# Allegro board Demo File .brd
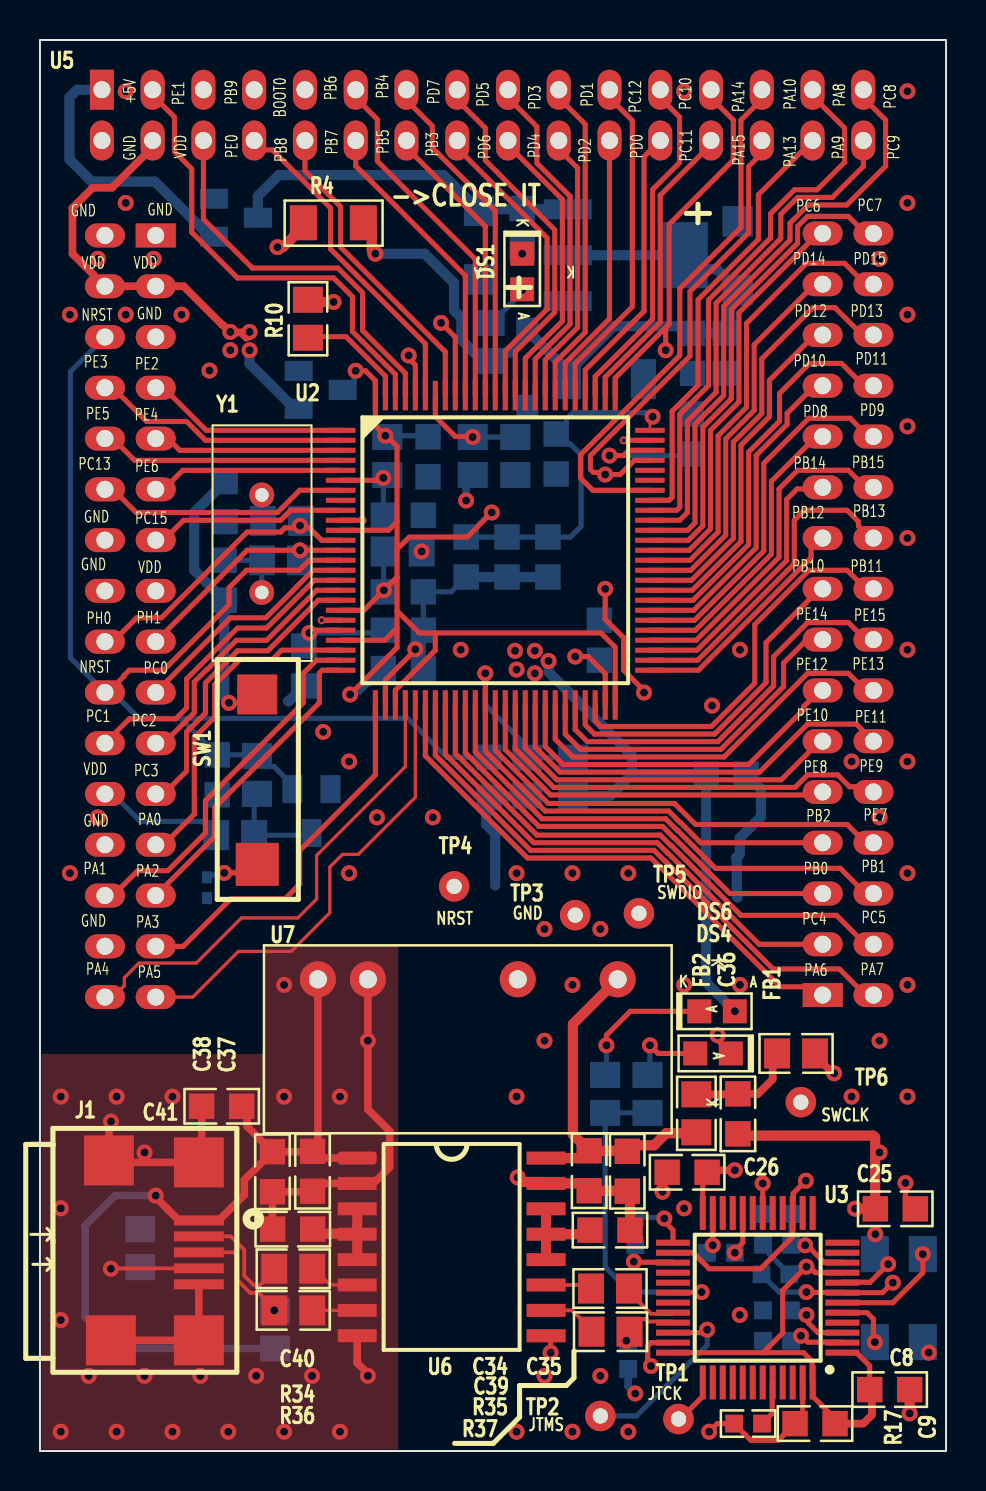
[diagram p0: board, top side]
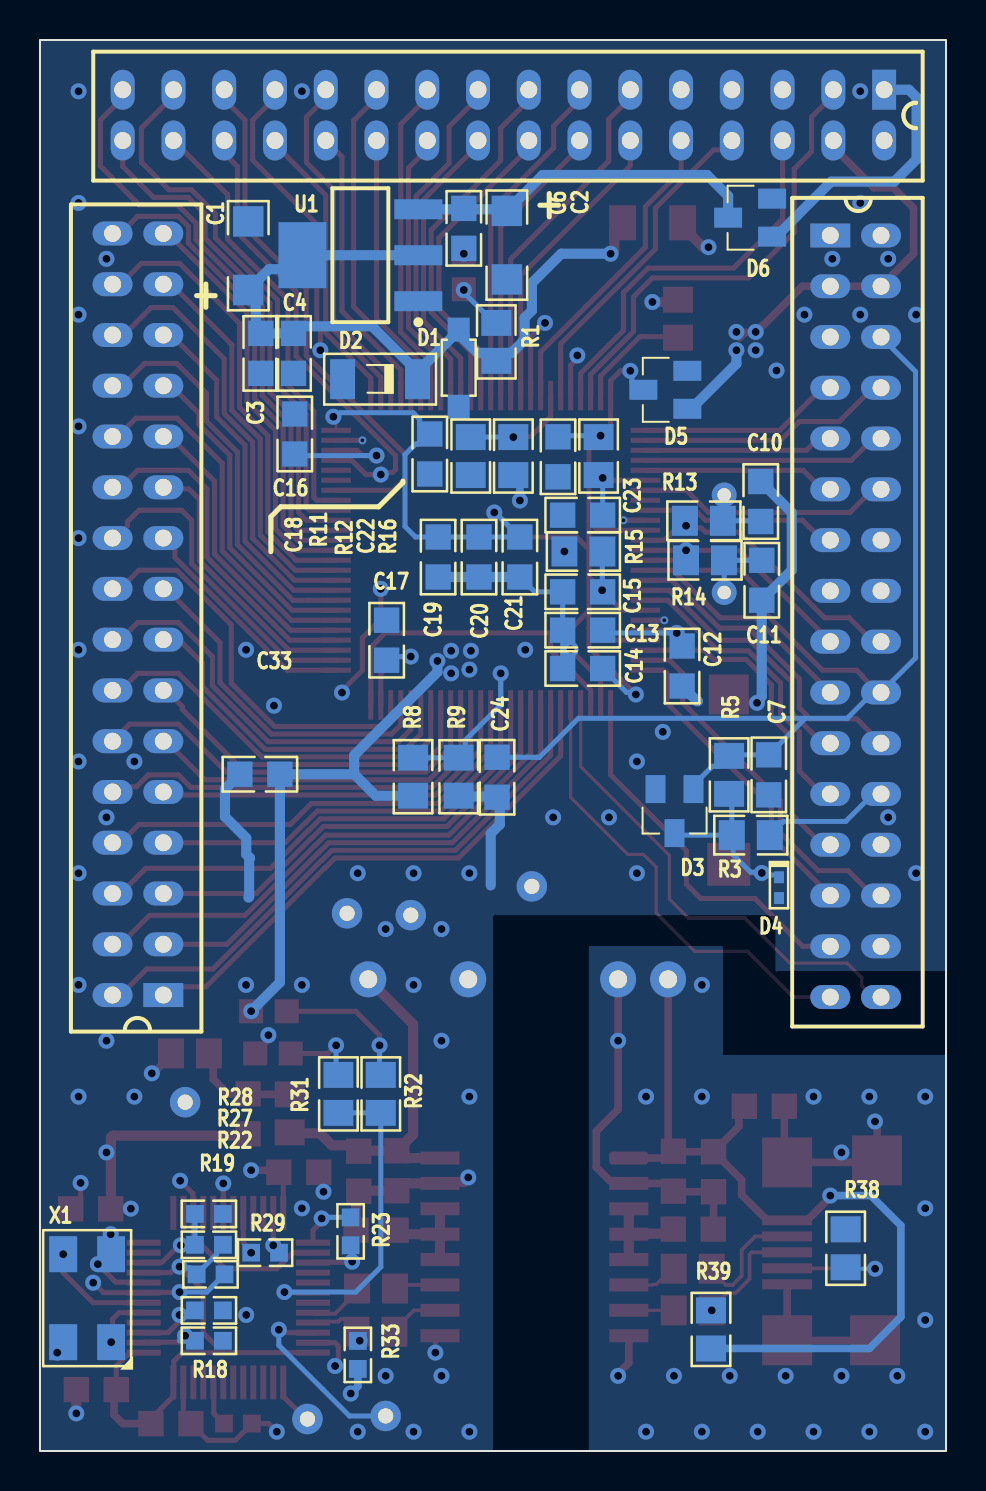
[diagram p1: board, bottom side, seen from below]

Outline 45.34 x 70.59 mm; copper layers: TOP, GND PLANE, L1, BOTTOM. Coordinates in mm from the lower left corner of the outline.
Outline path: rectangle 0,0 45.34,70.59

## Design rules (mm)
constraint set DEFAULT: min track width 0.127

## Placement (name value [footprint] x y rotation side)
C1  -  [CAP-T_1206]  34.92 59.79 90 bottom
C2  -  [CAP-T_1206]  21.97 60.32 270 bottom
C3  -  [CAP_0805]  34.29 54.91 90 bottom
C4  -  [CAP_0805]  32.65 54.91 90 bottom
C6  -  [CAP_0805]  24.13 61.16 90 bottom
C7  -  [CAP_0805]  8.87 33.82 90 bottom
C8  -  [CAP_0805]  42.52 3.07 180 top
C9  -  [CAP_0805]  38.78 1.37 0 top
C10  -  [CAP_0805]  9.27 47.5 90 bottom
C11  -  [CAP_0805]  9.22 43.56 270 bottom
C12  -  [CAP_0805]  13.21 39.27 90 bottom
C13  -  [CAP_0805]  18.18 41.06 180 bottom
C14  -  [CAP_0805]  18.18 39.15 0 bottom
C15  -  [CAP_0805]  18.18 42.98 0 bottom
C16  -  [CAP_0805]  32.59 50.88 270 bottom
C17  -  [CAP_0805]  27.99 40.56 270 bottom
C18  -  [CAP_0805]  25.83 49.88 90 bottom
C19  -  [CAP_0805]  25.42 44.72 90 bottom
C20  -  [CAP_0805]  23.37 44.72 90 bottom
C21  -  [CAP_0805]  21.32 44.72 90 bottom
C22  -  [CAP_0805]  19.42 49.74 90 bottom
C23  -  [CAP_0805]  18.18 46.82 0 bottom
C24  -  [CAP_0805]  22.47 33.71 90 bottom
C25  -  [CAP_0805]  42.8 12.12 0 top
C26  -  [CAP_0805]  32.38 13.94 0 top
C33  -  [CAP_0805]  34.33 33.86 180 bottom
C34  -  [CAP_0805]  27.48 14.02 90 top
C35  -  [CAP_0805]  29.39 14 90 top
C36  -  [CAP_0805]  34.92 16.87 90 top
C37  -  [CAP_0805]  13.64 14 90 top
C38  -  [CAP_0805]  11.63 13.97 90 top
C39  -  [CAP_0805]  28.52 11.05 0 top
C40  -  [CAP_0805]  12.65 11.1 180 top
C41  -  [CAP_0805]  9.09 17.25 180 top
D1  -  [DIO_SOD-123]  24.38 54.17 90 bottom
D2  -  [DIO_SOD80C]  28.32 53.62 0 bottom
D3  -  [SOT_23-3]  13.58 32.01 90 bottom
D4  -  [DIO_0402_SMD]  8.36 28.7 270 bottom
D5  -  [SOT_23-3]  14.05 53.09 180 bottom
D6  -  [SOT_23-3]  9.8 61.7 180 bottom
DS1  -  [LED_0805]  24.13 59 270 top
DS4  -  [LED_0805]  33.68 19.89 180 top
DS6  -  [LED_0805]  33.88 22 0 top
FB1  -  [IND_0805]  37.83 19.89 180 top
FB2  -  [IND_0805]  32.85 16.89 270 top
J1  -  [CON_690-005-299-043]  7.95 13.54 0 top
R1  -  [RES_0805]  22.5 55.48 270 bottom
R3  -  [RES_0805]  9.77 30.81 0 bottom
R4  -  [RES_1206]  14.68 61.44 0 top
R5  -  [RES_0805]  10.86 33.82 270 bottom
R8  -  [RES_0805]  26.67 33.73 90 bottom
R9  -  [RES_0805]  24.38 33.73 270 bottom
R10  -  [RES_0805]  13.41 56.64 270 top
R11  -  [RES_0805]  23.78 49.77 90 bottom
R12  -  [RES_0805]  21.65 49.77 270 bottom
R13  -  [RES_0805]  12.12 46.53 0 bottom
R14  -  [RES_0805]  12.06 44.56 0 bottom
R15  -  [RES_0805]  18.15 45 180 bottom
R16  -  [RES_0805]  17.39 49.77 90 bottom
R17  -  [RES_0603]  35.43 1.37 180 top
R18  -  [RES_0603]  36.88 5.52 180 bottom
R19  -  [RES_0603]  36.88 7.04 180 bottom
R22  -  [RES_0603]  36.8 8.84 0 bottom
R23  -  [RES_0603]  29.79 10.99 270 bottom
R27  -  [RES_0603]  36.88 10.32 0 bottom
R28  -  [RES_0603]  36.88 11.86 0 bottom
R29  -  [RES_0603]  34.07 9.92 0 bottom
R31  -  [RES_0805]  30.4 17.87 270 bottom
R32  -  [RES_0805]  28.28 17.87 270 bottom
R33  -  [RES_0603]  29.43 4.81 90 bottom
R34  -  [RES_0805]  12.67 9.12 180 top
R35  -  [RES_0805]  28.52 8.13 180 top
R36  -  [RES_0805]  12.67 7.04 180 top
R37  -  [RES_0805]  28.55 5.97 180 top
R38  -  [RES_0805]  5.02 10.14 270 bottom
R39  -  [RES_0805]  11.76 6.08 90 bottom
SW1  -  [SW_342_SMD]  10.87 37.85 90 top
TP1  -  [TEST_POINT_30]  31.95 1.6 0 top
TP2  -  [TEST_POINT_30]  28.04 1.75 0 top
TP3  -  [TEST_POINT_30]  26.78 26.81 0 top
TP4  -  [TEST_POINT_30]  20.73 28.24 0 top
TP5  -  [TEST_POINT_30]  29.97 26.9 0 top
TP6  -  [TEST_POINT_30]  38.07 17.45 0 top
U1  -  [SOT223_3]  29.28 59.79 0 bottom
U2  -  [QFN100_19_6_669_58X10_SMD]  22.78 44.93 0 top
U3  -  [LQFP-48_19_6_393_58X11_SMD]  35.92 7.67 180 top
U5  -  [MOD_PRJ-01-07-R070_TH]  5.79 60.81 0 top
U6  -  [SOICW16_50_440_25X76_SMT]  20.6 10.21 0 top
U7  -  [SPU03L-05_100_787_35D70_TH]  28.91 23.6 180 top
X1  -  [ABMM2_94_4_267_71X55_SMD]  42.98 7.65 90 bottom
Y1  -  [XTAL_193_184X455_TH]  11.1 47.83 270 top

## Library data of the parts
C1 C2 = CAP-T_1206
C3 C4 C6-C26 C33-C41 = CAP_0805
D1 = DIO_SOD-123
D2 = DIO_SOD80C
D3 D5 D6 = SOT_23-3
D4 = DIO_0402_SMD
DS1 DS4 DS6 = LED_0805
FB1 FB2 = IND_0805
J1 = CON_690-005-299-043
R1 R3 R5 R8-R16 R31 R32 R34-R39 = RES_0805
R4 = RES_1206
R17-R19 R22 R23 R27-R29 R33 = RES_0603
SW1 = SW_342_SMD
TP1-TP6 = TEST_POINT_30
U1 = SOT223_3
U2 = QFN100_19_6_669_58X10_SMD
U3 = LQFP-48_19_6_393_58X11_SMD
U5 = MOD_PRJ-01-07-R070_TH
U6 = SOICW16_50_440_25X76_SMT
U7 = SPU03L-05_100_787_35D70_TH
X1 = ABMM2_94_4_267_71X55_SMD
Y1 = XTAL_193_184X455_TH

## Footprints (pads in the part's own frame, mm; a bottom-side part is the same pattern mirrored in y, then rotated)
ABMM2_94_4_267_71X55_SMD
  rect 1.8x1.4 smd: 1(-2.2,-1.2) 2(2.2,-1.2) 3(2.2,1.2) 4(-2.2,1.2)
CAP-T_1206
  rect 1.524x1.524 smd: 1(-1.714,-0.005) 2(1.715,-0.005)
CAP_0805
  rect 1.27x1.27 smd: 1(-1,0) 2(1,0)
CON_690-005-299-043
  rect 2.5x0.5 smd: 1(0,-2) 2(0,-2.8) 3(0,-3.6) 4(0,-4.4) 5(0,-5.2)
  rect 2.5x2.5 smd: 6(0,0.9) 6_1(0,-8) 6_2(-4.5,1) 6_3(-4.4,-8)
DIO_0402_SMD
  rect 0.6x0.5 smd: A(1.041,0) K(0,0)
DIO_SOD80C
  rect 1.25x2 smd: A(1.875,0) K(-1.875,0)
DIO_SOD-123
  rect 1.2x1.1 smd: A(-1.938,0.006) K(1.923,0.006)
IND_0805
  rect 1.3x1.5 smd: 1(0.95,0) 2(-0.95,0)
LED_0805
  rect 1.2x1.2 smd: A(0.889,0) K(-0.889,0)
LQFP-48_19_6_393_58X11_SMD
  rect 1.7x0.3 smd: 1(-4.238,2.75) 2(-4.238,2.25) 3(-4.238,1.75) 4(-4.238,1.25) 5(-4.238,0.75) 6(-4.238,0.25) 7(-4.238,-0.25) 8(-4.238,-0.75) 9(-4.238,-1.25) 10(-4.238,-1.75) 11(-4.238,-2.25) 12(-4.238,-2.75) 25(4.238,-2.75) 26(4.238,-2.25) 27(4.238,-1.75) 28(4.238,-1.25) 29(4.238,-0.75) 30(4.238,-0.25) 31(4.238,0.25) 32(4.238,0.75) 33(4.238,1.25) 34(4.238,1.75) 35(4.238,2.25) 36(4.238,2.75)
  rect 0.3x1.7 smd: 13(-2.75,-4.238) 14(-2.25,-4.238) 15(-1.75,-4.238) 16(-1.25,-4.238) 17(-0.75,-4.238) 18(-0.25,-4.238) 19(0.25,-4.238) 20(0.75,-4.238) 21(1.25,-4.238) 22(1.75,-4.238) 23(2.25,-4.238) 24(2.75,-4.238) 37(2.75,4.238) 38(2.25,4.238) 39(1.75,4.238) 40(1.25,4.238) 41(0.75,4.238) 42(0.25,4.238) 43(-0.25,4.238) 44(-0.75,4.238) 45(-1.25,4.238) 46(-1.75,4.238) 47(-2.25,4.238) 48(-2.75,4.238)
MOD_PRJ-01-07-R070_TH
  rect 2x1.2 hole 0.85: 1(0,0) 65(33.376,-37.998)
  oval 2x1.2 hole 0.85: 2(-2.54,0) 3(0,-2.54) 4(-2.54,-2.54) 5(0,-5.08) 6(-2.54,-5.08) 7(0,-7.62) 8(-2.54,-7.62) 9(0,-10.16) 10(-2.54,-10.16) 11(0,-12.7) 12(-2.54,-12.7) 13(0,-15.24) 14(-2.54,-15.24) 15(0,-17.78) 16(-2.54,-17.78) 17(0,-20.32) 18(-2.54,-20.32) 19(0,-22.86) 20(-2.54,-22.86) 21(0,-25.4) 22(-2.54,-25.4) 23(0,-27.94) 24(-2.54,-27.94) 25(0,-30.48) 26(-2.54,-30.48) 27(0,-33.02) 28(-2.54,-33.02) 29(0,-35.56) 30(-2.54,-35.56) 31(0,-38.1) 32(-2.54,-38.1) 66(35.916,-37.998) 67(33.376,-35.458) 68(35.916,-35.458) 69(33.376,-32.918) 70(35.916,-32.918) 71(33.376,-30.378) 72(35.916,-30.378) 73(33.376,-27.838) 74(35.916,-27.838) 75(33.376,-25.298) 76(35.916,-25.298) 77(33.376,-22.758) 78(35.916,-22.758) 79(33.376,-20.218) 80(35.916,-20.218) 81(33.376,-17.678) 82(35.916,-17.678) 83(33.376,-15.138) 84(35.916,-15.138) 85(33.376,-12.598) 86(35.916,-12.598) 87(33.376,-10.058) 88(35.916,-10.058) 89(33.376,-7.518) 90(35.916,-7.518) 91(33.376,-4.978) 92(35.916,-4.978) 93(33.376,-2.438) 94(35.916,-2.438) 95(33.376,0.102) 96(35.916,0.102)
  rect 1.2x2 hole 0.85: 33(-2.692,7.29)
  oval 1.2x2 hole 0.85: 34(-2.692,4.75) 35(-0.152,7.29) 36(-0.152,4.75) 37(2.388,7.29) 38(2.388,4.75) 39(4.928,7.29) 40(4.928,4.75) 41(7.468,7.29) 42(7.468,4.75) 43(10.008,7.29) 44(10.008,4.75) 45(12.548,7.29) 46(12.548,4.75) 47(15.088,7.29) 48(15.088,4.75) 49(17.628,7.29) 50(17.628,4.75) 51(20.168,7.29) 52(20.168,4.75) 53(22.708,7.29) 54(22.708,4.75) 55(25.248,7.29) 56(25.248,4.75) 57(27.788,7.29) 58(27.788,4.75) 59(30.328,7.29) 60(30.328,4.75) 61(32.868,7.29) 62(32.868,4.75) 63(35.408,7.29) 64(35.408,4.75)
QFN100_19_6_669_58X10_SMD
  rect 1.475x0.254 smd: 1(-7.738,6.127) 2(-7.738,5.627) 3(-7.738,5.127) 4(-7.738,4.627) 5(-7.738,4.127) 6(-7.738,3.627) 7(-7.738,3.127) 8(-7.738,2.627) 9(-7.738,2.127) 10(-7.738,1.627) 11(-7.738,1.127) 12(-7.738,0.627) 13(-7.738,0.127) 14(-7.738,-0.373) 15(-7.738,-0.873) 16(-7.738,-1.373) 17(-7.738,-1.873) 18(-7.738,-2.373) 19(-7.738,-2.873) 20(-7.738,-3.373) 21(-7.738,-3.873) 22(-7.738,-4.373) 23(-7.738,-4.873) 24(-7.738,-5.373) 25(-7.738,-5.873) 51(7.738,-5.873) 52(7.738,-5.373) 53(7.738,-4.873) 54(7.738,-4.373) 55(7.738,-3.873) 56(7.738,-3.373) 57(7.738,-2.873) 58(7.738,-2.373) 59(7.738,-1.873) 60(7.738,-1.373) 61(7.738,-0.873) 62(7.738,-0.373) 63(7.738,0.127) 64(7.738,0.627) 65(7.738,1.127) 66(7.738,1.627) 67(7.738,2.127) 68(7.738,2.627) 69(7.738,3.127) 70(7.738,3.627) 71(7.738,4.127) 72(7.738,4.627) 73(7.738,5.127) 74(7.738,5.627) 75(7.738,6.127)
  rect 0.254x1.475 smd: 26(-6,-7.611) 27(-5.5,-7.611) 28(-5,-7.611) 29(-4.5,-7.611) 30(-4,-7.611) 31(-3.5,-7.611) 32(-3,-7.611) 33(-2.5,-7.611) 34(-2,-7.611) 35(-1.5,-7.611) 36(-1,-7.611) 37(-0.5,-7.611) 38(0,-7.611) 39(0.5,-7.611) 40(1,-7.611) 41(1.5,-7.611) 42(2,-7.611) 43(2.5,-7.611) 44(3,-7.611) 45(3.5,-7.611) 46(4,-7.611) 47(4.5,-7.611) 48(5,-7.611) 49(5.5,-7.611) 50(6,-7.611) 76(6,7.865) 77(5.5,7.865) 78(5,7.865) 79(4.5,7.865) 80(4,7.865) 81(3.5,7.865) 82(3,7.865) 83(2.5,7.865) 84(2,7.865) 85(1.5,7.865) 86(1,7.865) 87(0.5,7.865) 88(0,7.865) 89(-0.5,7.865) 90(-1,7.865) 91(-1.5,7.865) 92(-2,7.865) 93(-2.5,7.865) 94(-3,7.865) 95(-3.5,7.865) 96(-4,7.865) 97(-4.5,7.865) 98(-5,7.865) 99(-5.5,7.865) 100(-6,7.865)
RES_0603
  rect 0.889x0.889 smd: 1(-0.699,0) 2(0.699,0)
RES_0805
  rect 1.3x1.5 smd: 1(0.95,0) 2(-0.95,0)
RES_1206
  rect 1.35x1.75 smd: 1(1.5,0) 2(-1.5,0)
SOICW16_50_440_25X76_SMT
  custom 0.163x0.163 smd: 1(-4.725,4.445)
  rect 1.95x0.65 smd: 2(-4.725,3.175) 3(-4.725,1.905) 4(-4.725,0.635) 5(-4.725,-0.635) 6(-4.725,-1.905) 7(-4.725,-3.175) 8(-4.725,-4.445) 9(4.725,-4.445) 10(4.725,-3.175) 11(4.725,-1.905) 12(4.725,-0.635) 13(4.725,0.635) 14(4.725,1.905) 15(4.725,3.175) 16(4.725,4.445)
SOT223_3
  rect 2.4x1 smd: 1(-2.875,2.275) 2(-2.875,-0.025) 3(-2.875,-2.325)
  rect 2.4x3.3 smd: 4(2.925,-0.025)
SOT_23-3
  rect 1.4x1 smd: 1(1.1,-0.95) 2(1.1,0.95) 3(-1.1,0)
SPU03L-05_100_787_35D70_TH
  round 1.8 hole 0.9: 1(15,0) 2(12.5,0) 3(5,0) 4(0,0)
SW_342_SMD
  rect 2x2 smd: 1(0,0)
  rect 2.15x2.15 smd: 2(-8.5,0)
TEST_POINT_30
  round 1.524 hole 0.762: 1(0,0)
XTAL_193_184X455_TH
  round 1.247 hole 0.68: 1(0,0) 2(4.88,0)

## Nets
+3V3: C1.1 C3.2 C4.2 D1.K D2.K R1.1 R4.1 U1.2 U1.4
+5V: C2.1 C6.2 D6.3 U1.3
+5V_P: C34.2 C35.2 FB2.1 U6.16 U7.4
+5V_PBUS: C37.2 C38.2 C41.1 J1.1 R39.2 U6.1 U7.1
GND_IN: C37.1 C38.1 C40.2 C41.2 J1.5 J1.6 J1.6_1 J1.6_2 J1.6_3 R38.2 U6.2 U6.8 U7.2
GND_ISO: C1.2 C2.2 C3.1 C4.1 C6.1 C7.1 C8.1 C9.1 C10.2 C11.2 C12.1 C13.1 C14.2 C15.2 C16.1 C17.1 C18.1 C19.1 C20.1 C21.1 C22.1 C23.2 C24.1 C25.1 C26.1 C33.1 C34.1 C35.1 C36.1 C39.2 D1.A D2.A D4.A DS1.K DS4.K R9.1 R10.2 R11.2 R17.2 R18.2 R19.2 R28.1 R29.1 SW1.1 TP3.1 U1.1 U2.10 U2.20 U2.27 U2.74 U3.8 U3.23 U3.35 U3.47 U5.1 U5.2 U5.5 U5.14 U5.16 U5.26 U5.30 U5.34 U6.9 U6.15 U7.3 X1.2 X1.4
VDD: C8.2 C9.2 C26.2 C33.2 D5.1 DS6.A R3.2 R4.2 R8.2 R12.1 R22.2 R27.1 U3.1 U3.9 U3.24 U3.36 U3.48 U5.3 U5.4 U5.15 U5.24 U5.36
AIN_1: R27.2 R28.2 U3.10
BOOT0: R11.1 R12.2 U2.94 U5.39
D1_N: J1.2 R34.1
D1_P: J1.3 R36.1 R39.1
D3_N: R35.2 U3.32
D3_P: R33.2 R37.2 U3.33
LED_STLINK: R31.1 R32.1 U3.30
NETC10_1: C10.1 R13.2 Y1.1
NETC11_1: C11.1 R14.2 Y1.2
NETC12_2: C12.2 C13.2 R15.2 U2.21
NETC14_1: C14.1 C15.1 C18.2 C19.2 C20.2 C21.2 C22.2 D5.3 R15.1 R16.1 U2.11 U2.19 U2.22 U2.28 U2.50 U2.75 U2.100
NETC16_2: C16.2 U2.73
NETC17_2: C17.2 U2.49
NETC23_1: C23.1 R16.2 U2.6
NETC25_2: C25.2 R22.1 U3.7
NETC36_2: C36.2 FB1.1 FB2.2
NETC39_1: C39.1 U6.12 U6.13 U6.14
NETC40_1: C40.1 U6.3 U6.4 U6.5
NETD3_3: D3.3 D4.K R3.1 R5.1 SW1.2
NETD6_1: D6.1 U5.33
NETDS1_A: DS1.A R1.2
NETDS4_A: DS4.A R31.2
NETDS6_K: DS6.K R32.2
NETFB1_2: FB1.2 R33.1
NETJ1_4: J1.4 R38.1
NETR10_1: R10.1 U2.99
NETR17_1: R17.1 U3.44
NETR18_1: R18.1 U3.2
NETR19_1: R19.1 U3.3
NETR23_1: R23.1 U3.25
NETR29_2: R29.2 U3.20
NETR34_2: R34.2 U6.6
NETR35_1: R35.1 U6.11
NETR36_2: R36.2 U6.7
NETR37_1: R37.1 U6.10
NETU3_5: U3.5 X1.1
NETU3_6: U3.6 X1.3
NRST: C7.2 C24.2 D3.1 R5.2 TP4.1 U2.14 U3.18 U5.6 U5.20
PA0: U2.23 U5.25
PA1: U2.24 U5.28
PA2: U2.25 U5.27
PA3: U2.26 U5.29
PA4: U2.29 U5.32
PA5: U2.30 U5.31
PA6: U2.31 U5.65
PA7: U2.32 U5.66
PA8: U2.67 U5.61
PA9: U2.68 U5.62
PA10: U2.69 U5.59
PA15: U2.77 U5.58
PB0: U2.35 U5.69
PB1: U2.36 U5.70
PB2: R8.1 R9.2 U2.37 U5.71
PB3: U2.89 U5.46
PB4: U2.90 U5.43
PB5: U2.91 U5.44
PB6: U2.92 U5.41
PB7: U2.93 U5.42
PB8: U2.95 U5.40
PB9: U2.96 U5.37
PB10: U2.47 U5.81
PB11: U2.48 U5.82
PB12: U2.51 U5.83
PB13: U2.52 U5.84
PB14: U2.53 U5.85
PB15: U2.54 U5.86
PC0: U2.15 U5.19
PC1: U2.16 U5.22
PC2: U2.17 U5.21
PC3: U2.18 U5.23
PC4: U2.33 U5.67
PC5: U2.34 U5.68
PC6: U2.63 U5.95
PC7: U2.64 U5.96
PC8: U2.65 U5.63
PC9: U2.66 U5.64
PC10: U2.78 U5.55
PC11: U2.79 U5.56
PC12: U2.80 U5.53
PC13: U2.7 U5.12
PC15: U2.9 U5.13
PD0: U2.81 U5.54
PD1: U2.82 U5.51
PD2: U2.83 U5.52
PD3: U2.84 U5.49
PD4: U2.85 U5.50
PD5: U2.86 U5.47
PD6: U2.87 U5.48
PD7: U2.88 U5.45
PD8: U2.55 U5.87
PD9: U2.56 U5.88
PD10: U2.57 U5.89
PD11: U2.58 U5.90
PD12: U2.59 U5.91
PD13: U2.60 U5.92
PD14: U2.61 U5.93
PD15: U2.62 U5.94
PE0: U2.97 U5.38
PE1: U2.98 U5.35
PE2: U2.1 U5.7
PE3: U2.2 U5.8
PE4: U2.3 U5.9
PE5: U2.4 U5.10
PE6: U2.5 U5.11
PE7: U2.38 U5.72
PE8: U2.39 U5.73
PE9: U2.40 U5.74
PE10: U2.41 U5.75
PE11: U2.42 U5.76
PE12: U2.43 U5.77
PE13: U2.44 U5.78
PE14: U2.45 U5.79
PE15: U2.46 U5.80
PH0-OSC_IN: R13.1 U2.12 U5.18
PH1-OSC_OUT: R14.1 U2.13 U5.17
STM_JTCK: TP1.1 U3.37
STM_JTMS: TP2.1 U3.34
SWCLK: TP6.1 U2.76 U3.15 U3.26 U5.57
SWDIO: R23.2 TP5.1 U2.72 U3.27 U5.60

Pads without a net: D3 2; D5 2; D6 2; U2 8 70 71; U3 4 11 12 13 14 16 17 19 21 22 28 29 31 38 39 40 41 42 43 45 46

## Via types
v1: diameter 0.8, hole 0.4, TOP to BOTTOM, 152 vias
v2: diameter 0.4, hole 0.2, TOP to BOTTOM, 3 vias

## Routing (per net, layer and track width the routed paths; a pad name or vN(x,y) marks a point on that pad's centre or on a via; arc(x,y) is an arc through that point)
+3V3: length 37.8
  TOP w0.508: R4.1 16.6,61.02 16.6,60.07 v1(16.78,59.89)
  BOTTOM w0.508: v1(16.78,59.89) 19.25,59.89 20.72,58.42 20.72,57.05 21.09,56.69 21.09,55.58 21.74,54.93 22.11,54.93 R1.1 22.9,54.93 23.44,54.93 24.09,55.58 24.09,55.8 D1.K 24.39,56.05 24.69,55.75 24.69,55.75 26.45,53.99 ; U1.2 U1.4 32.9,59.12 33.87,59.12 C1.1 34.54,57.71 34.54,56.16 C3.2 C4.2 32.3,56.27 28.72,56.27 26.45,53.99 ; 26.45,53.99 D2.K
+5V: length 17.8
  BOTTOM w0.508: U1.3 24.13,62.12 ; 24.13,62.12 C6.2 ; 24.13,62.12 22.06,62.12 C2.1 20.19,63.83 11.95,63.83 10.9,62.78 D6.3
+5V_P: length 18
  TOP w0.508: U6.16 27.12,14.66 C34.2 ; 32.8,15.9 FB2.1 32.8,15.9 ; 32.8,15.9 31.33,15.9 30.73,15.29 29.69,15.29 C35.2 29.36,15.02 C34.2 ; C34.2 26.67,15.84 26.67,21.36 U7.4
+5V_PBUS: length 43.3
  TOP w0.381: U7.1 13.91,15.26 C37.2 ; v1(5.79,12.78) 5.79,12.7 6.95,11.54 J1.1 8.95,11.54 10.23,12.81 10.23,13.56 C38.2 ; C38.2 10.36,16.24 10.36,16.98 C41.1 ; C38.2 13.61,14.97 C37.2 ; U6.1 13.98,14.66 C37.2
  BOTTOM w0.381: R39.2 3.84,5.13 2.26,6.71 2.26,11.28 3.76,12.78 v1(5.79,12.78) 5.89,12.78
GND_IN: length 37.1
  TOP w0.381: 3.66,16.59 v1(3.55,16.48) 3.45,16.38 J1.6_2 3.55,14.44 J1.6 8.09,14.58 C41.2 ; J1.5 J1.6_1 J1.6_3 ; U7.2 v1(16.41,20.52) 16.41,17.09 17.5,16 17.5,14.2 16.82,13.52 16.01,13.52 U6.2 14.03,13.39 13.61,12.97 C38.1 11.63,11.12 C40.2 ; U6.8 15.87,4.41 16.41,3.87 v1(16.41,3.76)
  vias: v1(1.04,17.73) v1(1.04,12.14) v1(1.04,6.55) v1(1.04,0.97) v1(2.44,3.76) v1(3.84,17.73) v1(3.84,0.97) v1(5.23,14.94) v1(5.23,3.76) v1(6.63,17.73) v1(6.63,0.97) v1(8.03,3.76) v1(9.42,0.97) v1(10.82,3.76) v1(12.22,23.32) v1(12.22,17.73) v1(12.22,0.97) v1(13.61,3.76) v1(15.01,17.73) v1(15.01,0.97)
GND_ISO: length 88.6
  TOP w0.254: v1(33.49,0.97) 33.89,1.37 R17.2 35.57,0.53 36.95,0.53 C9.1 38.17,1.75 U3.47 ; v1(9.46,37.43) 10.45,37.43 SW1.1 ; U3.35 30.58,5.42 30.41,5.25 30.41,4.42 v1(30.57,4.26) ; v1(42.44,9.35) 41.54,8.44 40.18,8.44 U3.8 ; v2(14.1,41.56) U2.20 ; v1(33.91,20.8) 33.91,20.55 DS4.K ; v1(31.15,12.97) 31.15,13.71 C26.1 ; v1(25.55,4.92) 25.55,5.57 25.35,5.77 U6.9 ; v1(18.78,40.11) 18.78,40.08 17.28,38.57 U2.27 ; v2(29.2,50.56) U2.74 ; v1(33.67,10.29) U3.23 ; U2.10 v2(16.14,46.56)
  TOP w0.508: C36.1 35.01,15.78 41.69,15.78 41.78,15.69 41.79,15.68 41.79,12.12 ; 41.79,12.12 C25.1 ; 41.79,12.12 v1(40.79,12.12) ; R10.2 13.48,57.66 13.66,57.48 v1(14.69,57.48) ; v1(43.52,1.88) C8.1 ; C39.2 29.52,12.86 C35.1 29.36,13.02 C34.1 27.12,13.39 U6.15 25.25,13.46 24.14,13.46 v1(23.91,13.69)
  BOTTOM w0.254: v1(33.67,10.29) 33.38,10 R29.1 ; 17.2,43 17.2,45 ; C21.1 20.58,42.98 C15.2 C13.1 C14.2
  BOTTOM w0.508: 22.78,28.3 22.78,30.89 22.33,31.34 22.33,32.57 C24.1 22.5,32.74 24.35,32.74 R9.1 ; C21.1 C20.1 C19.1 ; C12.1 12.45,37.51 12.41,37.51 ; C10.2 7.72,46.95 7.72,44.06 C11.2 9.22,37.74 9.46,37.51 v1(9.46,37.43) ; X1.2 41.79,9.86 41.79,10.83 v1(41.8,10.85) ; 34.91,27.69 34.87,27.72 34.87,29.63 34.83,29.67 35.02,29.85 35.02,30.67 36.08,31.73 36.08,33.11 C33.1
  vias: v1(1.5,56.85) v1(1.5,28.91) v1(2.9,59.64) v1(2.9,31.7) v1(4.29,68.02) v1(4.29,62.43) v1(4.29,56.85) v1(5.69,59.64) v1(7.09,56.85) v1(8.48,54.05) v1(15.47,34.49) v1(15.47,28.91) v1(16.87,31.7) v1(19.66,31.7) v1(21.06,40.08) v1(23.85,28.91) v1(23.85,17.73) v1(23.85,0.97) v1(24.13,59.89) v1(25.25,26.11) v1(25.25,20.52) v1(25.25,3.76) v1(26.64,28.91) v1(26.64,23.32) v1(26.64,0.97) v1(28.04,26.11) v1(28.04,3.76) v1(29.44,28.91) v1(29.44,0.97) v1(32.23,68.02) v1(32.23,23.32) v1(32.23,12.14) v1(33.63,37.29) v1(35.03,40.08) v1(35.03,23.32) v1(35.02,6.81) v1(40.61,34.49) v1(40.61,17.73) v1(42.01,59.64) v1(42.01,31.7) v1(42.01,20.52) v1(42.01,14.94) v1(43.41,68.02) v1(43.41,62.43) v1(43.41,56.85) v1(43.41,51.26) v1(43.41,45.67) v1(43.41,40.08) v1(43.41,34.49) v1(43.41,28.91) v1(43.41,23.32) v1(43.41,17.73) v1(44.48,4.92)
VDD: length 162.8
  TOP w0.254: 36.18,4.92 U3.36 ; 36.18,4.92 38.21,4.92 38.64,4.49 38.64,3.46 U3.48 38.67,2.73 39.52,1.88 39.66,1.88 40.17,1.37 C9.2 ; 36.18,4.92 37.17,5.9 37.17,8.03 v1(38.35,9.22) 38.5,9.22 38.8,8.92 U3.9 ; 33.49,14.05 C26.2 33.17,13.73 U3.24 ; U3.1 40.85,4.92 41.52,4.26 C8.2 41.63,2.96
  TOP w0.381: 10.33,55.69 10.07,55.96 9.5,55.96 9.5,55.99 9.16,56.33 9.13,56.33 7.19,58.27 U5.3 U5.4 3.07,58.27 2.69,58.65 2.69,58.82 1.63,59.89 1.63,62.18 2.64,63.2 3.61,63.2 5.64,65.23 U5.36 ; v1(34.77,14.05) 33.49,14.05 ; 40.17,1.37 41.2,1.37 41.63,1.8 41.63,2.96
  TOP w0.508: v1(11.89,60.22) 12.16,60.22 13.18,61.24 R4.2
  L1 w0.381: 34.77,16.15 v1(34.77,22) ; 34.77,16.15 34.85,16.15 37.38,13.62 37.38,9.85 37.93,9.3 38.27,9.3 v1(38.35,9.22) ; 34.77,16.15 v1(34.77,14.05) ; 5.39,43.03 4.04,41.68 2.21,41.68 1.73,41.2 1.73,34.39 2.69,33.42
  L1 w0.508: 20.19,47.55 20.19,44.1 24.77,39.52 v1(25.45,39.52) ; 20.19,47.55 14.68,47.55 10.49,51.74 ; 20.19,47.55 v1(21.32,47.55) ; 10.49,51.74 9.68,50.93 9.68,46.91 6.35,43.58 6.35,43.41 5.97,43.03 U5.15 5.39,43.03 ; 10.49,51.74 v1(10.49,55.07) ; 2.69,33.42 2.69,33.25 3.07,32.87 U5.24 ; v1(10.49,55.98) 10.49,58.83 v1(11.89,60.22)
  BOTTOM w0.254: R3.2 8.82,30.91 8.3,31.43 8.2,31.43 8.13,31.5 5.02,31.5 3.65,32.87 U5.24 ; R27.1 36.5,10 36.5,9.84 R22.2 37.82,9.16 38.29,9.16 v1(38.35,9.22)
  BOTTOM w0.381: v1(21.32,47.55) 21.32,48.5 21.65,48.82 R12.1
  BOTTOM w0.508: 29.62,33.86 28.54,32.78 R8.2 ; 29.62,33.86 29.62,34.8 25.45,38.97 v1(25.45,39.52) ; 29.62,33.86 C33.2 33.33,23.44 v1(34.77,22) ; 12.99,52.09 D5.1 12.75,52.14 10.49,54.39 v1(10.49,55.07)
  vias: v1(9.52,55.98) v1(9.52,55.07) v1(23.77,40.03) v1(23.85,39.09) v1(24.77,40.03) v1(24.77,38.9)
AIN_1: length 4.5
  TOP w0.254: v1(38.29,10.29) 38.38,10.29 39.23,9.44 40.13,9.44 U3.10
  BOTTOM w0.254: R28.2 R27.2 38.27,10.32 v1(38.29,10.29)
BOOT0: length 27.9
  TOP w0.254: U2.94 19.78,51.75 20.78,50.75 21.62,50.75 v1(21.65,50.72)
  L1 w0.254: v1(21.65,50.72) 20.78,50.72 19.76,51.74 19.76,55.35 12.04,63.07 12.04,66.38 10.72,67.7 U5.39
  BOTTOM w0.254: R11.1 v1(21.65,50.72)
D1_N: length 5.9
  TOP w0.19: R34.1 11.72,9.02 11.01,8.31 10.68,8.31 10.23,8.76 10.23,10.06 9.54,10.74 J1.2
D1_P: length 5.8
  TOP w0.19: J1.3 9.72,9.94 9.83,9.83 9.83,8.6 10.52,7.91 10.97,7.91 10.97,7.89 11.72,7.14 v1(11.72,7.04)
D3_N: length 2.8
  TOP w0.19: R35.2 30.03,7.57 30.03,7.41 30.57,6.87 31.62,6.87 U3.32
D3_P: length 3
  TOP w0.19: v1(29.34,5.52) R37.2 29.5,6.04 30.05,6.6 30.29,6.6 30.41,6.47 31.62,6.47 U3.33
LED_STLINK: length 16.6
  TOP w0.254: U3.30 33.08,7.92 v1(33.11,7.95)
  BOTTOM w0.254: R31.1 30.4,16.92 R32.1 28.28,9.21 29.54,7.95 v1(33.11,7.95)
NETC10_1: length 3.7
  TOP w0.254: 11.1,47.33 Y1.1
  BOTTOM w0.254: C10.1 9.31,46.53 R13.2 11.1,46.6 Y1.1
NETC11_1: length 3.5
  BOTTOM w0.254: Y1.2 11.1,44.41 R14.2 C11.1
NETC12_2: length 14.5
  TOP w0.254: U2.21 13.61,41.06 v1(13.48,40.92)
  L1 w0.254: v1(13.48,40.92) 16.46,40.92 19.1,43.56 v1(19.1,45)
  BOTTOM w0.254: 17.04,40.92 v1(13.48,40.92) 13.21,40.66 C12.2 ; 17.04,40.92 C13.2 17.04,40.92
NETC14_1: length 77.4
  TOP w0.127: U2.75 30.52,51.6 v1(30.66,51.74)
  TOP w0.254: U2.50 28.78,40.21 28.07,40.92 19.78,40.92 ; 17.87,46.49 17.87,50.26 17.34,50.79 v1(17.28,50.79) 16.78,51.29 U2.100 16.78,53.54 16.29,54.04 v1(15.8,54.04) ; 17.87,46.49 17.44,46.06 U2.11 ; 17.87,46.49 17.87,45.1 ; 17.87,43.72 17.87,45.1 ; 17.87,43.72 v1(17.21,43.06) 16.21,42.06 U2.19 ; 17.87,43.72 17.87,42.03 ; 17.87,45.1 18.48,45.72 21.38,45.72 v1(22.61,46.95) ; 17.87,41.17 17.87,40.19 v1(15.52,37.85) ; 17.87,41.17 17.26,40.56 U2.22 ; 17.87,41.17 17.87,42.03 ; 19.78,40.92 18.97,40.92 17.87,42.03 ; 19.78,40.92 19.78,40.06 17.78,38.06 U2.28 ; v1(30.66,51.74) 30.66,51.75
  BOTTOM w0.254: v1(17.21,43.06) 17.2,43.06 ; v1(15.52,37.85) 15.62,37.95 15.99,37.95 C14.1 ; C22.2 19.36,50.79 v1(17.28,50.79) ; v1(22.61,46.95) 22.55,46.95 C21.2 C20.2 C19.2 26.54,45.72 27.08,46.25 27.08,49.84 26.8,50.12 26.55,50.37 26.47,50.37 26.29,50.55 26.29,50.63 C18.2 26.34,51.38 26.34,51.61 26.67,51.94 30.31,51.94 30.51,51.74 v1(30.66,51.74) ; C15.1 17.2,43 ; D5.3 15.35,53.09 15.72,53.46 15.72,53.96 v1(15.8,54.04)
NETC16_2: length 6.3
  TOP w0.254: v1(28.5,49.8) 29.2,49.8 29.47,50.06 U2.73
  BOTTOM w0.254: C16.2 32.51,49.8 v1(28.5,49.8)
NETC17_2: length 4.7
  TOP w0.254: v1(26.78,39.74) 27.44,39.74 28.28,38.89 U2.49
  BOTTOM w0.254: v1(26.78,39.74) 27.81,39.74 C17.2
NETC23_1: length 7
  TOP w0.254: v1(17.18,48.68) 17.06,48.56 U2.6
  BOTTOM w0.127: R16.2 17.18,48.62 C23.1
  BOTTOM w0.254: 17.39,48.68 v1(17.18,48.68) 17.32,48.82 R16.2 ; 17.39,48.68 R16.2 ; 17.39,48.68 17.18,48.48 C23.1 ; 17.39,48.68 R16.2
NETC25_2: length 14
  TOP w0.254: v1(42.68,8.42) 42.66,8.42 42.16,7.92 U3.7 40.14,7.94 38.37,7.94 v1(38.35,7.95) ; C25.2 43.31,12.61 v1(43.31,13.41)
  L1 w0.254: v1(43.31,13.41) 43.31,9.05 v1(42.68,8.42)
  BOTTOM w0.254: 38.41,7.95 v1(38.35,7.95) 37,7.95 R22.1
NETC36_2: length 5.5
  TOP w0.381: FB1.1 36.67,19.67 36.67,18.6 35.93,17.87 C36.2 34.9,17.84 FB2.2
NETC39_1: length 4.8
  TOP w0.508: C39.1 27.32,10.85 U6.13 ; U6.13 U6.14 ; U6.13 U6.12
NETC40_1: length 4.9
  TOP w0.508: U6.4 U6.3 ; U6.4 15.85,10.87 13.88,10.87 C40.1 ; U6.4 U6.5
NETD3_3: length 10.7
  TOP w0.254: SW1.2 10.44,28.92 v1(9.22,28.92)
  BOTTOM w0.254: R5.1 10.72,32.74 R3.1 ; 9.26,28.96 9.12,28.81 8.47,28.81 D4.K ; 9.26,28.96 9.78,28.96 10.65,29.83 10.65,30.74 R3.1 ; 9.26,28.96 v1(9.22,28.92) ; R3.1 13.48,30.81 D3.3
NETD6_1: length 13.7
  BOTTOM w0.508: U5.33 1.85,68.1 1.47,67.72 1.47,64.62 2.59,63.5 5.75,63.5 8.5,60.75 D6.1
NETDS1_A: length 2.4
  BOTTOM w0.254: v1(24.13,58.08) 24.13,57.96 22.6,56.43 R1.2
NETDS4_A: length 4
  TOP w0.254: v1(30.52,20.29) 30.93,19.89 DS4.A
  BOTTOM w0.254: R31.2 30.4,18.82 30.52,18.93 v1(30.52,20.29)
NETDS6_K: length 7.2
  TOP w0.254: v1(28.35,20.29) 28.35,20.8 29.54,22 DS6.K
  BOTTOM w0.254: v1(28.35,20.29) 28.35,18.88 R32.2
NETFB1_2: length 28.4
  TOP w0.381: 38.32,20.35 FB1.2 38.78,19.79 39.68,18.89 v1(39.74,18.89)
  L1 w0.381: v1(29.79,2.88) 37.98,2.88 39.75,4.65 39.75,18.75 v1(39.74,18.89)
  BOTTOM w0.381: R33.1 29.43,3.23 v1(29.79,2.88)
NETJ1_4: length 5.9
  TOP w0.19: J1.4 3.57,9.14 v1(3.55,9.12)
  BOTTOM w0.19: R38.1 4.95,9.12 v1(3.55,9.12)
NETR10_1: length 5.8
  TOP w0.254: U2.99 17.28,53.78 15.31,55.74 13.41,55.74 ; 13.41,55.74 13.38,55.74 ; 13.41,55.74 R10.1
NETR17_1: length 2.3
  TOP w0.254: U3.44 36.64,3.41 36.64,1.88 R17.1
NETR18_1: length 3.2
  TOP w0.254: U3.2 40.13,5.44 38.42,5.44 38.1,5.77 v1(38.08,5.77)
  BOTTOM w0.254: R18.1 37.83,5.77 v1(38.08,5.77) 38.1,5.77 38.35,5.51
NETR19_1: length 3.2
  TOP w0.254: U3.3 38.93,5.92 38.46,6.39 38.46,6.7 v1(38.35,6.81)
  BOTTOM w0.254: v1(38.35,6.81) 37.81,6.81 R19.1
NETR23_1: length 2.9
  TOP w0.254: v1(31.24,11.63) 31.24,11.49 31.68,11.05 U3.25
  BOTTOM w0.254: v1(31.24,11.63) 31.19,11.69 R23.1
NETR29_2: length 2.2
  TOP w0.254: v1(34.77,9.92) 34.77,10.03 35.17,10.42 U3.20
NETR34_2: length 2.6
  TOP w0.162: R34.2 13.72,9.12 14.5,8.33 14.67,8.33 14.69,8.31 U6.6
NETR35_1: length 2.3
  TOP w0.19: R35.1 27.4,8.31 U6.11
NETR36_2: length 2.3
  TOP w0.162: R36.2 U6.7
NETR37_1: length 2.8
  TOP w0.19: U6.10 26.63,7.04 27.6,6.07 27.6,5.97 R37.1
NETU3_5: length 2.9
  TOP w0.254: v1(41.78,5.45) 41.71,5.52 41.71,6.6 41.38,6.92 U3.5
NETU3_6: length 5.6
  TOP w0.254: U3.6 42.68,7.42 44.18,8.92 v1(44.18,9.85)
NRST: length 121.8
  TOP w0.254: U3.18 v1(36.17,13.39) ; U5.20 3.4,37.95 4.19,38.74 4.19,38.78 4.47,39.06 6.18,39.06 9.46,42.33 9.46,43.18 10.33,44.06 12.98,44.06 13.48,44.56 U2.14
  L1 w0.254: TP4.1 20.73,25.84 ; 20.73,25.84 9.92,36.65 4.95,36.65 3.65,37.95 U5.20 ; 20.73,25.84 21.32,25.25 21.32,22.88 25.55,18.65 25.55,10.85 28.4,8 31.97,8 32.86,8.89 35.48,8.89 36.17,9.57 v1(36.17,13.39)
  BOTTOM w0.254: C24.2 20.48,34.71 20.46,34.69 20.36,34.69 18.4,36.65 7.04,36.65 ; 7.04,36.65 C7.2 10.8,34.82 R5.2 11.38,34.25 11.7,34.25 12.63,33.31 D3.1 ; 7.04,36.65 4.95,36.65 3.65,37.95 U5.20 3.11,37.95 2.67,38.38 2.67,38.53 1.52,39.67 1.52,54 2.67,55.15 2.67,55.29 3.11,55.73 U5.6
PA0: length 16.5
  TOP w0.254: U5.25 6.19,30.33 7.72,31.86 7.72,35.69 8.74,36.71 8.74,38.33 10.01,39.6 11.63,39.6 12.09,40.06 U2.23
PA1: length 18.5
  TOP w0.254: U5.28 3.65,27.79 4.9,29.03 6.4,29.03 8.28,30.92 8.28,32.53 13.18,37.43 13.18,38.9 13.83,39.56 U2.24
PA2: length 15.7
  TOP w0.254: U2.25 14.13,39.06 13.98,38.91 13.98,37.43 8.74,32.19 8.74,30.74 6.37,28.37 6.37,28.22 5.94,27.79 U5.27
PA3: length 19
  TOP w0.254: U5.29 7.17,25.25 9.56,27.64 12.28,27.64 13,28.35 13,30.04 16.78,33.82 U2.26
PA4: length 24.4
  TOP w0.162: U2.29 18.28,34.23 13.84,29.79 13.84,27.61 12.9,26.67 10.08,26.67 7.82,24.41 4.95,24.41 4.22,23.68 4.22,23.28 3.65,22.71 U5.32
PA5: length 23.1
  TOP w0.162: U5.31 7.65,22.71 9.93,24.99 12.57,24.99 14.5,26.92 14.5,29.21 15.14,29.84 15.93,29.84 18.78,32.7 U2.30
PA6: length 27.4
  TOP w0.254: U2.31 19.28,34.78 24.39,29.67 30.57,29.67 31.09,29.15 31.11,29.15 37.04,23.22 38.75,23.22 U5.65
PA7: length 29.4
  TOP w0.254: U2.32 19.78,34.82 24.55,30.05 30.73,30.05 31.25,29.53 31.27,29.53 36.68,24.11 40,24.11 41.31,22.81 U5.66
PA8: length 27.2
  TOP w0.254: U2.67 31.87,47.06 32.02,47.21 32.02,51.86 33.45,53.3 33.45,57.58 36.56,60.69 36.56,61.9 37.76,63.09 38.89,63.09 40.27,64.47 40.27,66.18 39.4,67.05 38.66,67.79 U5.61
PA9: length 22
  TOP w0.254: U2.68 31.49,47.56 31.63,47.71 31.63,52.02 32.93,53.32 32.93,57.6 35.95,60.61 35.95,62.85 38.08,64.98 38.22,64.98 38.66,65.41 U5.62
PA10: length 26.9
  TOP w0.254: U2.69 27.67,48.06 27.05,48.68 27.05,49.84 32.02,54.81 32.02,58.15 35.08,61.21 35.08,66.58 36.12,67.62 U5.59
PA15: length 15
  TOP w0.254: U2.77 28.28,53.72 31.04,56.47 31.04,62.82 33.58,65.36 U5.58
PB0: length 23.2
  TOP w0.254: U2.35 21.28,34.93 24.97,31.25 31.15,31.25 31.72,30.67 31.74,30.67 34.52,27.89 U5.69
PB1: length 25.2
  TOP w0.254: U2.36 21.78,34.97 25.13,31.63 31.31,31.63 31.88,31.05 31.9,31.05 33.8,29.15 40.05,29.15 41.31,27.89 U5.70
PB2: length 30.1
  TOP w0.254: v1(22.28,38.9) U2.37 22.28,35.01 25.28,32.01 31.46,32.01 32.04,31.44 32.06,31.44 33.06,30.43 U5.71
  BOTTOM w0.254: R8.1 R9.2 24.05,35.01 24.05,35.56 22.28,37.33 v1(22.28,38.9)
PB3: length 14.4
  TOP w0.254: U5.46 18.34,65.21 22.28,61.26 U2.89
PB4: length 17.8
  TOP w0.254: U2.90 21.78,59.62 18.21,63.2 16.88,64.53 16.88,66.61 15.8,67.7 U5.43
PB5: length 15
  TOP w0.254: U5.44 15.8,64.29 17.83,62.26 21.28,58.8 U2.91
PB6: length 18.5
  TOP w0.254: U2.92 20.78,55.72 v1(20.07,56.43)
  L1 w0.254: U5.41 13.26,67.7 14.69,66.26 14.69,64 20.07,58.62 v1(20.07,56.43) 20.07,56.4
PB7: length 15.7
  TOP w0.254: U2.93 20.28,54.98 18.04,57.23 15.05,60.22 15.05,62.25 13.26,64.04 U5.42
PB8: length 16.6
  TOP w0.254: U5.40 10.72,65.52 11.16,65.09 11.63,65.09 14.54,62.18 14.54,60.13 19.28,55.39 U2.95
PB9: length 19.8
  TOP w0.254: v1(18.45,54.81) 18.45,54.66 18.78,54.32 U2.96
  L1 w0.254: U5.37 8.18,67.7 9.4,66.48 9.4,63.86 13.28,59.98 v1(18.45,54.81)
  BOTTOM w0.254: 18.35,54.91 v1(18.45,54.81)
PB10: length 17.2
  TOP w0.254: U5.81 39.02,43.13 36.33,40.44 36.33,38.44 33.76,35.86 27.75,35.86 27.28,36.33 U2.47
PB11: length 20.2
  TOP w0.254: U5.82 41.32,43.13 40.39,44.06 38.49,44.06 35.77,41.34 35.77,38.41 33.6,36.25 28.07,36.25 27.78,36.53 U2.48
PB12: length 11.7
  TOP w0.254: U5.83 39.02,45.67 38.59,45.23 38.59,44.69 32.95,39.06 U2.51
PB13: length 16.3
  TOP w0.254: U5.84 41.56,45.67 40.95,46.28 40.95,46.5 40.39,47.06 38.25,47.06 37.74,46.56 37.74,44.39 32.91,39.56 U2.52
PB14: length 13.8
  TOP w0.254: U5.85 39.02,48.21 38.94,48.13 37.89,48.13 37.36,47.61 37.36,44.55 32.87,40.06 U2.53
PB15: length 17.1
  TOP w0.254: U2.54 32.83,40.56 36.98,44.71 36.98,48.13 37.91,49.06 38.41,49.06 38.41,49.06 40.45,49.06 41.3,48.21 U5.86
PC0: length 11.8
  TOP w0.254: U2.15 13.66,44.06 12.83,43.22 12.83,43.21 11.3,41.68 9.52,41.68 U5.19
PC1: length 16.1
  TOP w0.254: U5.22 3.4,35.41 3.83,35.84 3.83,35.99 4.47,36.63 6.79,36.63 7.34,37.17 7.34,38.63 9.88,41.17 11.34,41.17 13.73,43.56 U2.16
PC2: length 13.3
  TOP w0.254: U2.17 13.84,43.06 11.34,40.56 9.83,40.56 8.33,39.06 8.31,39.06 7.72,38.47 7.72,36.94 6.19,35.41 U5.21
PC3: length 15.3
  TOP w0.254: U2.18 13.93,42.56 11.4,40.03 9.89,40.03 8.28,38.42 8.28,36.91 7.34,35.97 7.34,34.01 6.19,32.87 U5.23
PC4: length 25.3
  TOP w0.254: U2.33 20.28,34.86 24.71,30.43 30.89,30.43 31.41,29.91 31.42,29.91 35.99,25.35 U5.67
PC5: length 27.3
  TOP w0.254: U2.34 20.78,34.89 24.87,30.81 31.05,30.81 31.57,30.29 31.58,30.29 35.08,26.8 39.86,26.8 41.31,25.35 U5.68
PC6: length 20.7
  TOP w0.254: U5.95 38.94,60.91 34.98,56.95 34.98,52.48 33.55,51.06 33.55,46.13 32.48,45.06 U2.63
PC7: length 24.3
  TOP w0.254: U5.96 41.31,60.91 40.45,61.76 38.41,61.76 37.91,61.26 37.91,60.42 34.59,57.1 34.59,52.64 33.18,51.23 33.17,51.23 33.17,46.29 32.45,45.56 U2.64
PC8: length 29.6
  TOP w0.254: U5.63 41.2,67.7 42.32,66.58 42.32,64.28 40.37,62.33 38.44,62.33 37.53,61.42 37.53,60.58 34.21,57.26 34.21,52.8 33.47,52.06 33.46,52.06 32.78,51.37 32.78,46.43 32.41,46.06 U2.65
PC9: length 25.3
  TOP w0.254: U5.64 41.2,64.26 39.65,62.71 37.91,62.71 37.07,61.87 37.07,60.66 33.83,57.42 33.83,52.97 32.4,51.53 32.4,46.95 32.01,46.56 U2.66
PC10: length 17.4
  TOP w0.254: U2.78 27.78,53.76 30.66,56.63 30.66,63.11 32.01,64.46 32.01,66.73 31.04,67.7 U5.55
PC11: length 14.4
  TOP w0.254: U5.56 31.04,65.41 30.6,64.98 30.46,64.98 30.23,64.74 30.23,57.02 27.28,54.08 U2.79
PC12: length 17
  TOP w0.254: U2.80 26.78,54.39 29.64,57.25 29.64,66.55 28.5,67.7 U5.53
PC13: length 12.7
  TOP w0.254: U2.7 13,48.06 11.89,46.95 4.81,46.95 3.65,48.11 U5.12
PC15: length 9.9
  TOP w0.254: U5.13 6.19,45.57 7.18,46.56 12.04,46.56 12.54,47.06 U2.9
PD0: length 13.7
  TOP w0.254: U2.81 26.28,54.43 28.5,56.64 U5.54
PD1: length 16.5
  TOP w0.254: U5.51 25.96,67.7 27.28,66.37 27.28,55.97 25.78,54.47 U2.82
PD2: length 13.8
  TOP w0.254: U5.52 25.96,65.13 26.9,64.18 26.9,56.21 25.28,54.59 U2.83
PD3: length 17.3
  TOP w0.254: U2.84 24.78,54.62 26.52,56.36 26.52,62.77 24.87,64.43 24.87,66.25 23.42,67.7 U5.49
PD4: length 14.7
  TOP w0.254: U5.50 23.42,65.33 26.14,62.61 26.14,56.52 24.28,54.66 U2.85
PD5: length 18.1
  TOP w0.254: U5.47 20.88,67.58 22.28,66.18 22.28,64.56 25.76,61.09 25.76,56.96 23.78,54.99 U2.86
PD6: length 15.5
  TOP w0.254: U2.87 23.28,55.03 25.38,57.12 25.38,60.68 20.88,65.18 U5.48
PD7: length 17.1
  TOP w0.254: U2.88 22.78,62.04 19.63,65.19 19.63,66.28 18.34,67.58 U5.45
PD8: length 14.8
  TOP w0.254: U5.87 38.84,50.75 36.6,48.51 36.6,44.87 32.8,41.06 U2.55
PD9: length 18.3
  TOP w0.254: U2.56 32.76,41.56 36.22,45.02 36.22,49.41 38.47,51.66 40.54,51.66 41.45,50.75 U5.88
PD10: length 16.3
  TOP w0.254: U2.57 32.72,42.06 35.84,45.18 35.84,49.81 37.39,51.36 37.39,51.91 38.77,53.29 U5.89
PD11: length 20.1
  TOP w0.254: U2.58 31.9,42.56 31.91,42.55 32.67,42.55 35.46,45.34 35.46,49.97 37.01,51.52 37.01,52.91 38.51,54.41 40.11,54.41 41.22,53.29 U5.90
PD12: length 17.8
  TOP w0.254: U2.59 32.64,43.06 35.08,45.5 35.08,50.32 36.5,51.74 36.5,53.56 38.77,55.83 U5.91
PD13: length 21.8
  TOP w0.254: U5.92 41.15,55.83 39.78,57.2 38.68,57.2 36.12,54.64 36.12,51.9 34.7,50.48 34.7,45.65 32.6,43.56 U2.60
PD14: length 19.3
  TOP w0.254: U2.61 32.56,44.06 34.32,45.81 34.32,50.63 35.74,52.06 35.74,55.34 38.77,58.37 U5.93
PD15: length 23.1
  TOP w0.254: U2.62 32.52,44.56 33.93,45.97 33.93,50.79 35.36,52.21 35.36,56.41 38.35,59.41 40.27,59.41 41.31,58.37 U5.94
PE0: length 19.5
  TOP w0.254: U5.38 8.18,61.63 10.63,59.18 14.91,59.18 16.14,57.94 16.14,56.05 18.28,53.91 U2.97
PE1: length 23.1
  TOP w0.254: U5.35 5.64,67.82 6.73,66.73 6.73,65 7.59,64.14 7.59,60.97 9.88,58.68 14.69,58.68 15.64,57.74 15.64,56 17.78,53.86 U2.98
PE2: length 10.1
  TOP w0.254: U2.1 8.32,51.06 6.19,53.19 U5.7
PE3: length 12.9
  TOP w0.254: U5.8 3.65,53.19 5.34,51.5 7.34,51.5 8.28,50.56 U2.2
PE4: length 9.5
  TOP w0.254: U5.9 6.4,50.65 6.99,50.06 U2.3
PE5: length 12.2
  TOP w0.254: U5.10 3.65,50.65 4.74,49.56 U2.4
PE6: length 9.6
  TOP w0.254: U5.11 6.19,48.11 7.14,49.06 U2.5
PE7: length 23.1
  TOP w0.254: U2.38 22.78,35.05 25.44,32.39 31.75,32.39 32.8,31.34 40.39,31.34 41.31,30.43 U5.72
PE8: length 19.1
  TOP w0.254: U2.39 23.28,35.09 25.56,32.82 39.01,32.82 U5.73
PE9: length 21.5
  TOP w0.254: U2.40 23.78,35.13 25.71,33.2 37.79,33.2 38.41,33.82 39.92,33.82 40.51,33.23 40.79,33.23 41.05,32.97 U5.74
PE10: length 18.5
  TOP w0.254: U5.75 39.02,35.51 37.09,33.58 25.87,33.58 24.28,35.17 U2.41
PE11: length 21
  TOP w0.254: U2.42 24.78,35.2 26.03,33.96 36.01,33.96 38.41,36.36 40.85,36.36 41.13,36.09 41.13,35.95 41.56,35.51 U5.76
PE12: length 18
  TOP w0.254: U2.43 25.28,35.24 26.19,34.34 35.46,34.34 38.22,37.1 38.22,37.24 39.02,38.05 U5.77
PE13: length 20.1
  TOP w0.254: U2.44 25.78,35.61 26.67,34.72 34.23,34.72 37.91,38.4 37.91,38.4 38.41,38.9 40.45,38.9 41.31,38.05 U5.78
PE14: length 17.6
  TOP w0.254: U2.45 26.28,35.86 27.05,35.1 34.07,35.1 37.21,38.24 37.21,39.42 38.2,40.41 38.99,40.41 U5.79
PE15: length 20.1
  TOP w0.254: U5.80 41.31,40.59 40.45,41.44 38.41,41.44 36.71,39.74 36.71,38.28 33.92,35.48 27.39,35.48 26.78,36.09 U2.46
PH0-OSC_IN: length 14.5
  TOP w0.254: U5.18 3.65,40.49 4.85,41.68 6.07,41.68 10.36,45.97 12.04,45.97 12.25,46.18 12.91,46.18 v1(13.01,46.29) 13.12,46.18 13.48,46.18 14.1,45.56 U2.12
PH1-OSC_OUT: length 11.2
  TOP w0.254: U2.13 v1(13.01,45.06) 10.36,45.06 6.37,41.07 6.37,40.92 5.94,40.49 U5.17
STM_JTCK: length 2.4
  TOP w0.254: U3.37 33.17,2.73 32.03,1.6 TP1.1
STM_JTMS: length 9.4
  TOP w0.254: v1(33.38,6.07) 33.24,5.92 U3.34 31.69,5.91
  BOTTOM w0.254: v1(33.38,6.07) 33.38,5.29 31.2,3.1 29.85,1.75 TP2.1
SWCLK: length 73.9
  TOP w0.254: 31.31,56.2 31.49,56.38 31.49,61.37 34.7,64.58 34.7,66.58 33.58,67.7 U5.57 ; 31.31,56.2 28.78,53.68 U2.76 ; 31.31,56.2 v1(31.31,55.07) ; v1(38.32,13.52) 37.69,12.88 37.69,12.59 37.67,12.57 U3.15 37.67,10.72 36.06,9.12 33.49,9.12 32.69,9.92 U3.26
  L1 w0.254: v1(31.31,55.07) 31.39,55.07 36.79,49.67 36.79,18.73 TP6.1 38.22,17.3 38.22,13.62 v1(38.32,13.52)
SWDIO: length 92.7
  TOP w0.254: v1(29.72,9.47) 29.75,9.44 31.65,9.44 U3.27 ; v1(28.28,43.13) 28.28,41.61 29.2,40.68 29.2,39.06 30.23,38.04 v1(30.23,37.94) ; U2.72 29.74,49.56 29.03,48.85 v1(28.28,48.85) 28.18,48.95 27.69,48.95 27.55,49.1 27.55,49.8 32.52,54.77 32.52,58 35.46,60.94 35.46,64.26 36.12,64.92 U5.60
  L1 w0.254: v1(28.28,48.85) v1(28.28,43.13) 28.28,39.71 24.59,36.02 14.21,36.02 v1(14.17,35.98) ; TP5.1 30.06,26.81 32.32,26.81 33.11,26.02 ; 33.11,26.02 33.11,35.06 v1(30.23,37.94) ; 33.11,26.02 33.11,10.85 31.74,9.47 v1(29.72,9.47)
  BOTTOM w0.254: R23.2 29.72,10.21 v1(29.72,9.47)

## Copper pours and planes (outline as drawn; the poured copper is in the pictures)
GND_IN on TOP: 17.92,25.3 17.93,25.29 17.93,0.08 0.07,0.08 0.05,0.1 0.07,0.13 0.07,19.86 11.2,19.86 11.21,19.88 11.21,25.3
GND_IN on BOTTOM: 17.87,25.25 17.88,25.24 17.88,0.03 0.03,0.03 0,0.05 0.03,0.08 0.03,19.81 11.15,19.81 11.17,19.83 11.17,25.25
GND_ISO on BOTTOM: 0,70.59 0.05,70.54 0.05,24.03 8.43,24.03 8.48,23.98 8.53,24.03 8.53,26.8 22.5,26.8 22.56,26.85 22.67,26.73 22.67,0 45.34,0 45.34,70.59
GND_ISO on GND PLANE: 44.83,11.48 40.51,11.48 40.51,8.46 37.97,8.46 37.97,6.3 40.51,6.3 40.51,3.38 44.83,3.38 44.83,0.51 22.58,0.51 22.58,26.72 7.75,26.72 7.75,21.01 0.51,21.01 0.51,70.08 44.83,70.08

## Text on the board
Board Geometry/Soldermask Top: @nymble Labs
Ref Des/Silkscreen Top: GND | PC13 | NRST | VDD | PA1 | PE3 | PE5 | PC1 | PA4 | PH0 | PC2 | PC3 | PE4 | PE2 | PE6 | PC15 | PA2 | PA3 | PH1 | PA5 | PA0 | PC0 | PB12 | PB10 | PD14 | PD10 | PB14 | PD12 | PE14 | PE12 | PC6 | PE10 | PC4 | PD8 | PE8 | PB0 | PA6 | PB2 | PD13 | PB11 | PB15 | PE13 | PB13 | PD15 | PE15 | PE11 | PD11 | PC7 | PE9 | PD9 | PA7 | PB1 | PC5 | PE7 | +5V | PE1 | PB9 | PE0 | BOOT0 | PB8 | PB6 | PB7 | PB4 | PB5 | PB3 | PD7 | PD5 | PD6 | PD4 | PD3 | PD2 | PD1 | PC12 | PD0 | PC10 | PC11 | PA14 | PA15 | PA13 | PA10 | PA9 | PA8 | PC8 | PC9 | JTMS | JTCK | SWDIO | SWCLK | ->CLOSE IT
